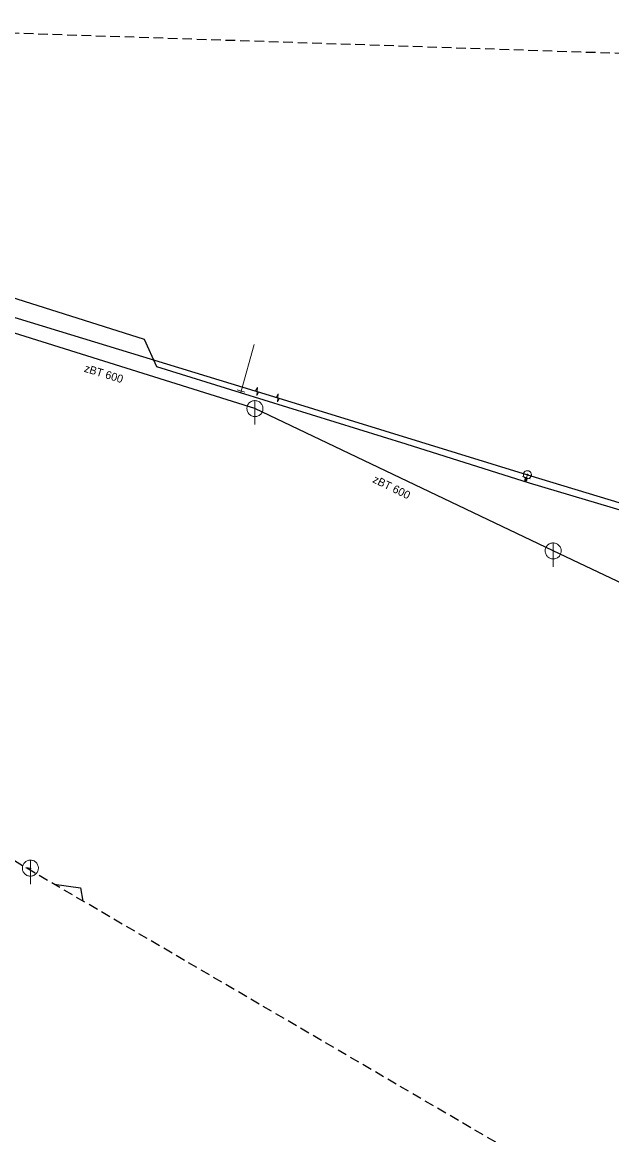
# Model space of a CAD drawing. Extents: x -774415 to -774100, y -975744 to -975502.
# Drawn here: x -774337 to -774263.4, y -975640.9 to -975501.9 of the extents above; entities that cross this region are included whole.
import ezdxf

# ---------------------------------------------------------------- set-up
doc = ezdxf.new("R2010")
doc.units = 0
doc.header["$LTSCALE"] = 0.4
doc.linetypes.add('MEDIUM_DASHED', pattern=[4.5, 3, -1.5])
for name, color, linetype, lineweight in [('1', 7, 'MEDIUM_DASHED', 25), ('13', 7, 'Continuous', 13), ('14', 7, 'Continuous', 13), ('17', 7, 'Continuous', 25), ('22', 7, 'Continuous', 13), ('34', 7, 'Continuous', 13), ('47', 7, 'Continuous', 13), ('9', 7, 'Continuous', 13)]:
    doc.layers.add(name, color=color, linetype=linetype, lineweight=lineweight)

msp = doc.modelspace()

# ---------------------------------------------------------------- linework, layer by layer
at = {"layer": '1'}
msp.add_lwpolyline([(-774414.714, -975561.823), (-774378.138, -975501.935), (-774197.267, -975507.964), (-774100.401, -975732.645), (-774205.708, -975744.301), (-774260.773, -975651.856)], close=True, dxfattribs=at)
at = {"layer": '13'}
msp.add_line((-774309.64, -975548.02), (-774308, -975542.201), dxfattribs=at)
at = {"layer": '14', "lineweight": 25}
for p, q in [((-774307.913, -975550.202), (-774342.839, -975539.266)), ((-774270.686, -975567.987), (-774307.913, -975550.202)), ((-774234.913, -975584.951), (-774270.686, -975567.987)), ((-774336.525, -975607.552), (-774335.944, -975607.612)), ((-774335.944, -975607.612), (-774335.977, -975607.873))]:
    msp.add_line(p, q, dxfattribs=at)
at = {"layer": '14'}
msp.add_line((-774309.699, -975548.23), (-774309.64, -975548.02), dxfattribs=at)
msp.add_lwpolyline([(-774273.912, -975558.461), (-774274.021, -975558.833), (-774274.118, -975559.127)], dxfattribs=at)
at = {"layer": '17'}
for p, q in [((-774307.632, -975548.061), (-774305.052, -975548.857)), ((-774305.052, -975548.857), (-774273.912, -975558.461))]:
    msp.add_line(p, q, dxfattribs=at)
for points in [[(-774190.98, -975675.3), (-774195.739, -975661.53), (-774202.46, -975642.109), (-774207.43, -975626.379), (-774211.07, -975615.34), (-774217.71, -975595.969), (-774219.62, -975590.41), (-774224.989, -975576.25), (-774225.51, -975574.5), (-774226.62, -975573.949), (-774228.079, -975573.359), (-774258.14, -975564.129), (-774273.649, -975559.52), (-774289.02, -975554.649), (-774309.699, -975548.23), (-774320.17, -975544.98), (-774321.69, -975541.59), (-774344.199, -975534.469), (-774360.363, -975529.358), (-774373.359, -975525.199), (-774377.583, -975527.43), (-774378.039, -975527.68), (-774378.399, -975527.859), (-774381.76, -975529.64)], [(-774380.382, -975525.739), (-774379.171, -975526.114), (-774359.03, -975532.35), (-774307.92, -975547.973), (-774307.632, -975548.061)], [(-774273.912, -975558.461), (-774254.809, -975564.278), (-774226.618, -975573.011), (-774219.919, -975594.089), (-774205.166, -975638.503)], [(-774332.978, -975609.627), (-774329.668, -975610.067), (-774329.386, -975611.727)]]:
    msp.add_lwpolyline(points, dxfattribs=at)
at = {"layer": '22'}
for p, q in [((-774307.913, -975552.202), (-774307.912, -975549.202)), ((-774270.686, -975569.987), (-774270.685, -975566.987)), ((-774335.944, -975609.612), (-774335.943, -975606.612))]:
    msp.add_line(p, q, dxfattribs=at)
for points in [[(-774306.913, -975550.202), (-774306.918, -975550.093), (-774306.936, -975549.985), (-774306.966, -975549.879), (-774307.006, -975549.778), (-774307.058, -975549.681), (-774307.12, -975549.591), (-774307.192, -975549.508), (-774307.272, -975549.434), (-774307.36, -975549.368), (-774307.454, -975549.313), (-774307.554, -975549.268), (-774307.659, -975549.235), (-774307.766, -975549.213), (-774307.875, -975549.203), (-774307.985, -975549.205), (-774308.093, -975549.219), (-774308.2, -975549.244), (-774308.303, -975549.281), (-774308.401, -975549.33), (-774308.493, -975549.388), (-774308.579, -975549.457), (-774308.656, -975549.534), (-774308.725, -975549.62), (-774308.784, -975549.712), (-774308.832, -975549.81), (-774308.869, -975549.913), (-774308.895, -975550.02), (-774308.909, -975550.128), (-774308.912, -975550.238), (-774308.902, -975550.347), (-774308.881, -975550.454), (-774308.847, -975550.558), (-774308.803, -975550.658), (-774308.748, -975550.753), (-774308.682, -975550.841), (-774308.608, -975550.921), (-774308.525, -975550.993), (-774308.435, -975551.055), (-774308.339, -975551.107), (-774308.237, -975551.148), (-774308.132, -975551.178), (-774308.024, -975551.196), (-774307.914, -975551.202), (-774307.805, -975551.196), (-774307.697, -975551.178), (-774307.592, -975551.149), (-774307.49, -975551.108), (-774307.393, -975551.056), (-774307.303, -975550.994), (-774307.22, -975550.923), (-774307.145, -975550.843), (-774307.08, -975550.755), (-774307.024, -975550.661), (-774306.98, -975550.561), (-774306.946, -975550.457), (-774306.924, -975550.349), (-774306.914, -975550.24)], [(-774269.686, -975567.987), (-774269.691, -975567.878), (-774269.709, -975567.77), (-774269.739, -975567.664), (-774269.779, -975567.563), (-774269.831, -975567.466), (-774269.893, -975567.376), (-774269.965, -975567.293), (-774270.045, -975567.219), (-774270.133, -975567.153), (-774270.227, -975567.098), (-774270.327, -975567.053), (-774270.432, -975567.02), (-774270.539, -975566.998), (-774270.648, -975566.988), (-774270.758, -975566.99), (-774270.866, -975567.004), (-774270.973, -975567.029), (-774271.076, -975567.066), (-774271.174, -975567.115), (-774271.266, -975567.173), (-774271.352, -975567.242), (-774271.429, -975567.319), (-774271.498, -975567.405), (-774271.557, -975567.497), (-774271.605, -975567.595), (-774271.642, -975567.698), (-774271.668, -975567.805), (-774271.682, -975567.913), (-774271.685, -975568.023), (-774271.675, -975568.132), (-774271.654, -975568.239), (-774271.62, -975568.343), (-774271.576, -975568.443), (-774271.521, -975568.538), (-774271.455, -975568.626), (-774271.381, -975568.706), (-774271.298, -975568.778), (-774271.208, -975568.84), (-774271.112, -975568.892), (-774271.01, -975568.933), (-774270.905, -975568.963), (-774270.797, -975568.981), (-774270.687, -975568.987), (-774270.578, -975568.981), (-774270.47, -975568.963), (-774270.365, -975568.934), (-774270.263, -975568.893), (-774270.166, -975568.841), (-774270.076, -975568.779), (-774269.993, -975568.708), (-774269.918, -975568.628), (-774269.853, -975568.54), (-774269.797, -975568.446), (-774269.753, -975568.346), (-774269.719, -975568.242), (-774269.697, -975568.134), (-774269.687, -975568.025)], [(-774334.944, -975607.612), (-774334.949, -975607.503), (-774334.967, -975607.395), (-774334.997, -975607.289), (-774335.037, -975607.188), (-774335.089, -975607.091), (-774335.151, -975607.001), (-774335.223, -975606.918), (-774335.303, -975606.844), (-774335.391, -975606.778), (-774335.485, -975606.723), (-774335.585, -975606.678), (-774335.69, -975606.645), (-774335.797, -975606.623), (-774335.906, -975606.613), (-774336.016, -975606.615), (-774336.124, -975606.629), (-774336.231, -975606.654), (-774336.334, -975606.691), (-774336.432, -975606.74), (-774336.524, -975606.798), (-774336.61, -975606.867), (-774336.687, -975606.944), (-774336.756, -975607.03), (-774336.815, -975607.122), (-774336.863, -975607.22), (-774336.9, -975607.323), (-774336.926, -975607.43), (-774336.94, -975607.538), (-774336.943, -975607.648), (-774336.933, -975607.757), (-774336.912, -975607.864), (-774336.878, -975607.968), (-774336.834, -975608.068), (-774336.779, -975608.163), (-774336.713, -975608.251), (-774336.639, -975608.331), (-774336.556, -975608.403), (-774336.466, -975608.465), (-774336.37, -975608.517), (-774336.268, -975608.558), (-774336.163, -975608.588), (-774336.055, -975608.606), (-774335.945, -975608.612), (-774335.836, -975608.606), (-774335.728, -975608.588), (-774335.623, -975608.559), (-774335.521, -975608.518), (-774335.424, -975608.466), (-774335.334, -975608.404), (-774335.251, -975608.333), (-774335.176, -975608.253), (-774335.111, -975608.165), (-774335.055, -975608.071), (-774335.011, -975607.971), (-774334.977, -975607.867), (-774334.955, -975607.759), (-774334.945, -975607.65)]]:
    msp.add_lwpolyline(points, close=True, dxfattribs=at)
at = {"layer": '34'}
for p, q in [((-774310.116, -975547.869), (-774309.163, -975548.171)), ((-774274.5, -975558.692), (-774273.541, -975558.974))]:
    msp.add_line(p, q, dxfattribs=at)
at = {"layer": '47'}
for p, q in [((-774307.577, -975547.554), (-774307.823, -975548.001)), ((-774304.998, -975548.35), (-774305.244, -975548.797))]:
    msp.add_line(p, q, dxfattribs=at)
for points in [[(-774307.577, -975547.554), (-774307.686, -975548.567), (-774307.44, -975548.12)], [(-774304.998, -975548.35), (-774305.105, -975549.363), (-774304.859, -975548.916)]]:
    msp.add_lwpolyline(points, dxfattribs=at)
for points in [[(-774273.433, -975558.606), (-774273.421, -975558.556), (-774273.413, -975558.503), (-774273.412, -975558.452), (-774273.415, -975558.399), (-774273.424, -975558.347), (-774273.439, -975558.297), (-774273.459, -975558.249), (-774273.484, -975558.203), (-774273.513, -975558.16), (-774273.546, -975558.119), (-774273.584, -975558.082), (-774273.626, -975558.051), (-774273.67, -975558.023), (-774273.717, -975558), (-774273.766, -975557.982), (-774273.816, -975557.97), (-774273.869, -975557.962), (-774273.921, -975557.961), (-774273.973, -975557.964), (-774274.025, -975557.973), (-774274.075, -975557.988), (-774274.124, -975558.008), (-774274.17, -975558.033), (-774274.213, -975558.061), (-774274.253, -975558.095), (-774274.29, -975558.133), (-774274.322, -975558.175), (-774274.349, -975558.219), (-774274.372, -975558.266), (-774274.39, -975558.315), (-774274.402, -975558.365), (-774274.41, -975558.418), (-774274.412, -975558.47), (-774274.408, -975558.522), (-774274.399, -975558.574), (-774274.385, -975558.624), (-774274.365, -975558.673), (-774274.34, -975558.719), (-774274.311, -975558.762), (-774274.277, -975558.802), (-774274.239, -975558.839), (-774274.198, -975558.871), (-774274.153, -975558.898), (-774274.106, -975558.921), (-774274.057, -975558.939), (-774274.007, -975558.951), (-774273.954, -975558.959), (-774273.903, -975558.961), (-774273.85, -975558.957), (-774273.798, -975558.948), (-774273.748, -975558.934), (-774273.7, -975558.914), (-774273.654, -975558.889), (-774273.611, -975558.859), (-774273.57, -975558.826), (-774273.533, -975558.788), (-774273.502, -975558.747), (-774273.474, -975558.702), (-774273.451, -975558.655)], [(-774273.833, -975558.484), (-774273.83, -975558.476), (-774273.83, -975558.468), (-774273.83, -975558.459), (-774273.83, -975558.451), (-774273.832, -975558.442), (-774273.834, -975558.434), (-774273.837, -975558.426), (-774273.841, -975558.418), (-774273.846, -975558.411), (-774273.852, -975558.405), (-774273.858, -975558.398), (-774273.865, -975558.393), (-774273.872, -975558.389), (-774273.879, -975558.385), (-774273.888, -975558.382), (-774273.896, -975558.379), (-774273.904, -975558.379), (-774273.913, -975558.379), (-774273.921, -975558.379), (-774273.93, -975558.381), (-774273.938, -975558.383), (-774273.946, -975558.386), (-774273.954, -975558.39), (-774273.962, -975558.395), (-774273.967, -975558.401), (-774273.974, -975558.407), (-774273.979, -975558.414), (-774273.983, -975558.421), (-774273.987, -975558.428), (-774273.99, -975558.437), (-774273.993, -975558.445), (-774273.993, -975558.453), (-774273.993, -975558.462), (-774273.993, -975558.47), (-774273.991, -975558.479), (-774273.99, -975558.487), (-774273.986, -975558.495), (-774273.982, -975558.503), (-774273.977, -975558.511), (-774273.971, -975558.516), (-774273.965, -975558.523), (-774273.958, -975558.528), (-774273.951, -975558.532), (-774273.944, -975558.536), (-774273.935, -975558.539), (-774273.927, -975558.542), (-774273.919, -975558.542), (-774273.91, -975558.542), (-774273.902, -975558.542), (-774273.893, -975558.54), (-774273.885, -975558.539), (-774273.877, -975558.535), (-774273.869, -975558.531), (-774273.862, -975558.526), (-774273.856, -975558.52), (-774273.849, -975558.514), (-774273.844, -975558.507), (-774273.84, -975558.5), (-774273.836, -975558.493)]]:
    msp.add_lwpolyline(points, close=True, dxfattribs=at)
at = {"layer": '9'}
for points in [[(-774274.244, -975559.127), (-774274.244, -975559.14), (-774274.242, -975559.153), (-774274.239, -975559.166), (-774274.234, -975559.178), (-774274.228, -975559.19), (-774274.221, -975559.201), (-774274.213, -975559.211), (-774274.203, -975559.221), (-774274.193, -975559.229), (-774274.182, -975559.236), (-774274.17, -975559.242), (-774274.158, -975559.247), (-774274.145, -975559.25), (-774274.132, -975559.252), (-774274.119, -975559.254), (-774274.106, -975559.253), (-774274.093, -975559.251), (-774274.08, -975559.248), (-774274.068, -975559.243), (-774274.056, -975559.237), (-774274.045, -975559.23), (-774274.035, -975559.222), (-774274.025, -975559.212), (-774274.017, -975559.202), (-774274.01, -975559.191), (-774274.004, -975559.179), (-774273.999, -975559.167), (-774273.996, -975559.154), (-774273.994, -975559.141), (-774273.992, -975559.128), (-774273.993, -975559.115), (-774273.995, -975559.102), (-774273.998, -975559.089), (-774274.003, -975559.077), (-774274.009, -975559.065), (-774274.016, -975559.054), (-774274.024, -975559.044), (-774274.034, -975559.034), (-774274.044, -975559.026), (-774274.055, -975559.019), (-774274.067, -975559.013), (-774274.079, -975559.008), (-774274.092, -975559.005), (-774274.105, -975559.003), (-774274.118, -975559.002), (-774274.131, -975559.002), (-774274.144, -975559.004), (-774274.157, -975559.007), (-774274.169, -975559.012), (-774274.181, -975559.018), (-774274.192, -975559.025), (-774274.202, -975559.033), (-774274.212, -975559.043), (-774274.22, -975559.053), (-774274.227, -975559.064), (-774274.233, -975559.076), (-774274.238, -975559.088), (-774274.241, -975559.101), (-774274.243, -975559.114)], [(-774274.224, -975559.127), (-774274.225, -975559.138), (-774274.223, -975559.149), (-774274.22, -975559.16), (-774274.216, -975559.17), (-774274.211, -975559.18), (-774274.205, -975559.189), (-774274.198, -975559.198), (-774274.19, -975559.206), (-774274.181, -975559.213), (-774274.172, -975559.219), (-774274.162, -975559.224), (-774274.152, -975559.228), (-774274.141, -975559.231), (-774274.13, -975559.234), (-774274.119, -975559.234), (-774274.108, -975559.234), (-774274.097, -975559.232), (-774274.086, -975559.229), (-774274.076, -975559.225), (-774274.066, -975559.22), (-774274.057, -975559.214), (-774274.048, -975559.207), (-774274.04, -975559.199), (-774274.033, -975559.19), (-774274.027, -975559.181), (-774274.022, -975559.171), (-774274.018, -975559.161), (-774274.015, -975559.15), (-774274.013, -975559.139), (-774274.012, -975559.128), (-774274.012, -975559.117), (-774274.014, -975559.106), (-774274.017, -975559.095), (-774274.021, -975559.085), (-774274.026, -975559.075), (-774274.032, -975559.066), (-774274.039, -975559.057), (-774274.047, -975559.049), (-774274.056, -975559.042), (-774274.065, -975559.036), (-774274.075, -975559.031), (-774274.085, -975559.027), (-774274.096, -975559.024), (-774274.107, -975559.022), (-774274.118, -975559.022), (-774274.129, -975559.021), (-774274.14, -975559.023), (-774274.151, -975559.026), (-774274.161, -975559.03), (-774274.171, -975559.035), (-774274.18, -975559.041), (-774274.189, -975559.048), (-774274.197, -975559.056), (-774274.204, -975559.065), (-774274.21, -975559.074), (-774274.215, -975559.084), (-774274.219, -975559.094), (-774274.222, -975559.105), (-774274.224, -975559.116)], [(-774274.205, -975559.127), (-774274.205, -975559.136), (-774274.204, -975559.145), (-774274.201, -975559.154), (-774274.198, -975559.162), (-774274.194, -975559.17), (-774274.189, -975559.178), (-774274.183, -975559.185), (-774274.177, -975559.191), (-774274.17, -975559.197), (-774274.162, -975559.202), (-774274.154, -975559.206), (-774274.146, -975559.209), (-774274.137, -975559.212), (-774274.128, -975559.213), (-774274.119, -975559.215), (-774274.11, -975559.214), (-774274.101, -975559.213), (-774274.092, -975559.21), (-774274.084, -975559.207), (-774274.076, -975559.203), (-774274.068, -975559.198), (-774274.061, -975559.192), (-774274.055, -975559.186), (-774274.049, -975559.179), (-774274.044, -975559.171), (-774274.04, -975559.163), (-774274.037, -975559.155), (-774274.034, -975559.146), (-774274.033, -975559.137), (-774274.031, -975559.128), (-774274.032, -975559.119), (-774274.033, -975559.11), (-774274.036, -975559.101), (-774274.039, -975559.093), (-774274.043, -975559.085), (-774274.048, -975559.077), (-774274.054, -975559.07), (-774274.06, -975559.064), (-774274.067, -975559.058), (-774274.075, -975559.053), (-774274.083, -975559.049), (-774274.091, -975559.046), (-774274.1, -975559.043), (-774274.109, -975559.042), (-774274.118, -975559.041), (-774274.127, -975559.041), (-774274.136, -975559.042), (-774274.145, -975559.045), (-774274.153, -975559.048), (-774274.161, -975559.052), (-774274.169, -975559.057), (-774274.176, -975559.063), (-774274.182, -975559.069), (-774274.188, -975559.076), (-774274.193, -975559.084), (-774274.197, -975559.092), (-774274.2, -975559.1), (-774274.203, -975559.109), (-774274.204, -975559.118)], [(-774274.185, -975559.127), (-774274.185, -975559.134), (-774274.184, -975559.141), (-774274.183, -975559.148), (-774274.18, -975559.154), (-774274.177, -975559.16), (-774274.173, -975559.166), (-774274.169, -975559.172), (-774274.164, -975559.177), (-774274.158, -975559.181), (-774274.152, -975559.185), (-774274.146, -975559.188), (-774274.14, -975559.191), (-774274.133, -975559.192), (-774274.126, -975559.195), (-774274.119, -975559.195), (-774274.112, -975559.195), (-774274.105, -975559.193), (-774274.098, -975559.192), (-774274.092, -975559.189), (-774274.085, -975559.186), (-774274.08, -975559.182), (-774274.074, -975559.178), (-774274.069, -975559.173), (-774274.065, -975559.167), (-774274.061, -975559.161), (-774274.058, -975559.155), (-774274.055, -975559.149), (-774274.053, -975559.142), (-774274.052, -975559.135), (-774274.051, -975559.128), (-774274.051, -975559.121), (-774274.052, -975559.114), (-774274.054, -975559.107), (-774274.057, -975559.101), (-774274.06, -975559.094), (-774274.064, -975559.089), (-774274.068, -975559.083), (-774274.073, -975559.078), (-774274.079, -975559.074), (-774274.084, -975559.07), (-774274.091, -975559.067), (-774274.097, -975559.064), (-774274.104, -975559.062), (-774274.111, -975559.061), (-774274.118, -975559.061), (-774274.125, -975559.061), (-774274.132, -975559.061), (-774274.139, -975559.063), (-774274.145, -975559.066), (-774274.151, -975559.069), (-774274.157, -975559.073), (-774274.163, -975559.077), (-774274.168, -975559.082), (-774274.172, -975559.088), (-774274.176, -975559.093), (-774274.179, -975559.1), (-774274.182, -975559.106), (-774274.183, -975559.113), (-774274.185, -975559.12)], [(-774274.165, -975559.127), (-774274.165, -975559.132), (-774274.165, -975559.137), (-774274.164, -975559.142), (-774274.162, -975559.146), (-774274.16, -975559.151), (-774274.157, -975559.155), (-774274.154, -975559.158), (-774274.15, -975559.162), (-774274.147, -975559.165), (-774274.143, -975559.168), (-774274.138, -975559.17), (-774274.134, -975559.172), (-774274.129, -975559.173), (-774274.124, -975559.175), (-774274.119, -975559.175), (-774274.114, -975559.175), (-774274.109, -975559.174), (-774274.104, -975559.173), (-774274.1, -975559.171), (-774274.095, -975559.169), (-774274.091, -975559.166), (-774274.087, -975559.163), (-774274.084, -975559.159), (-774274.081, -975559.156), (-774274.078, -975559.152), (-774274.076, -975559.147), (-774274.074, -975559.143), (-774274.073, -975559.138), (-774274.072, -975559.133), (-774274.071, -975559.128), (-774274.071, -975559.123), (-774274.072, -975559.118), (-774274.073, -975559.113), (-774274.075, -975559.109), (-774274.077, -975559.104), (-774274.08, -975559.1), (-774274.083, -975559.096), (-774274.086, -975559.093), (-774274.09, -975559.09), (-774274.094, -975559.087), (-774274.099, -975559.085), (-774274.103, -975559.083), (-774274.108, -975559.082), (-774274.113, -975559.081), (-774274.118, -975559.081), (-774274.123, -975559.081), (-774274.128, -975559.082), (-774274.133, -975559.082), (-774274.137, -975559.084), (-774274.142, -975559.086), (-774274.146, -975559.089), (-774274.149, -975559.092), (-774274.153, -975559.095), (-774274.156, -975559.099), (-774274.159, -975559.103), (-774274.161, -975559.108), (-774274.163, -975559.112), (-774274.164, -975559.117), (-774274.165, -975559.122)], [(-774274.145, -975559.127), (-774274.145, -975559.13), (-774274.146, -975559.133), (-774274.145, -975559.135), (-774274.144, -975559.138), (-774274.143, -975559.141), (-774274.141, -975559.143), (-774274.139, -975559.145), (-774274.137, -975559.147), (-774274.135, -975559.149), (-774274.133, -975559.151), (-774274.13, -975559.153), (-774274.127, -975559.154), (-774274.125, -975559.154), (-774274.122, -975559.155), (-774274.119, -975559.155), (-774274.116, -975559.155), (-774274.113, -975559.155), (-774274.11, -975559.154), (-774274.108, -975559.153), (-774274.105, -975559.152), (-774274.103, -975559.15), (-774274.1, -975559.148), (-774274.098, -975559.146), (-774274.097, -975559.144), (-774274.095, -975559.142), (-774274.094, -975559.139), (-774274.092, -975559.136), (-774274.092, -975559.134), (-774274.091, -975559.131), (-774274.09, -975559.128), (-774274.091, -975559.125), (-774274.091, -975559.122), (-774274.092, -975559.119), (-774274.093, -975559.117), (-774274.094, -975559.114), (-774274.096, -975559.112), (-774274.097, -975559.109), (-774274.099, -975559.107), (-774274.102, -975559.106), (-774274.104, -975559.104), (-774274.107, -975559.103), (-774274.109, -975559.102), (-774274.112, -975559.101), (-774274.115, -975559.101), (-774274.118, -975559.1), (-774274.121, -975559.101), (-774274.124, -975559.1), (-774274.126, -975559.102), (-774274.129, -975559.102), (-774274.132, -975559.103), (-774274.134, -975559.105), (-774274.136, -975559.106), (-774274.138, -975559.108), (-774274.14, -975559.111), (-774274.142, -975559.113), (-774274.143, -975559.116), (-774274.144, -975559.118), (-774274.145, -975559.121), (-774274.145, -975559.124)], [(-774274.126, -975559.127), (-774274.126, -975559.129), (-774274.126, -975559.129), (-774274.125, -975559.129), (-774274.125, -975559.131), (-774274.126, -975559.132), (-774274.124, -975559.132), (-774274.124, -975559.132), (-774274.124, -975559.134), (-774274.124, -975559.134), (-774274.123, -975559.135), (-774274.121, -975559.135), (-774274.121, -975559.135), (-774274.121, -975559.136), (-774274.119, -975559.136), (-774274.119, -975559.136), (-774274.118, -975559.136), (-774274.117, -975559.136), (-774274.117, -975559.135), (-774274.116, -975559.135), (-774274.114, -975559.135), (-774274.114, -975559.134), (-774274.114, -975559.134), (-774274.113, -975559.133), (-774274.113, -975559.133), (-774274.111, -975559.132), (-774274.111, -975559.131), (-774274.11, -975559.13), (-774274.11, -975559.13), (-774274.11, -975559.129), (-774274.11, -975559.128), (-774274.11, -975559.127), (-774274.11, -975559.126), (-774274.11, -975559.126), (-774274.111, -975559.125), (-774274.111, -975559.124), (-774274.112, -975559.123), (-774274.112, -975559.123), (-774274.113, -975559.122), (-774274.113, -975559.122), (-774274.114, -975559.121), (-774274.115, -975559.121), (-774274.116, -975559.12), (-774274.116, -975559.12), (-774274.117, -975559.12), (-774274.118, -975559.12), (-774274.119, -975559.12), (-774274.12, -975559.12), (-774274.12, -975559.12), (-774274.121, -975559.121), (-774274.122, -975559.12), (-774274.123, -975559.122), (-774274.123, -975559.122), (-774274.124, -975559.122), (-774274.124, -975559.122), (-774274.125, -975559.124), (-774274.125, -975559.125), (-774274.125, -975559.126), (-774274.126, -975559.126), (-774274.126, -975559.127)]]:
    msp.add_lwpolyline(points, close=True, dxfattribs=at)

# ---------------------------------------------------------------- texts
at = {"layer": '1'}
for rotation, p in [(343, (-774329.308, -975545.582)), (334, (-774293.312, -975559.376))]:
    msp.add_text('zBT 600 ', height=1, rotation=rotation, dxfattribs=at).set_placement(p)

doc.saveas('drawing.dxf')
